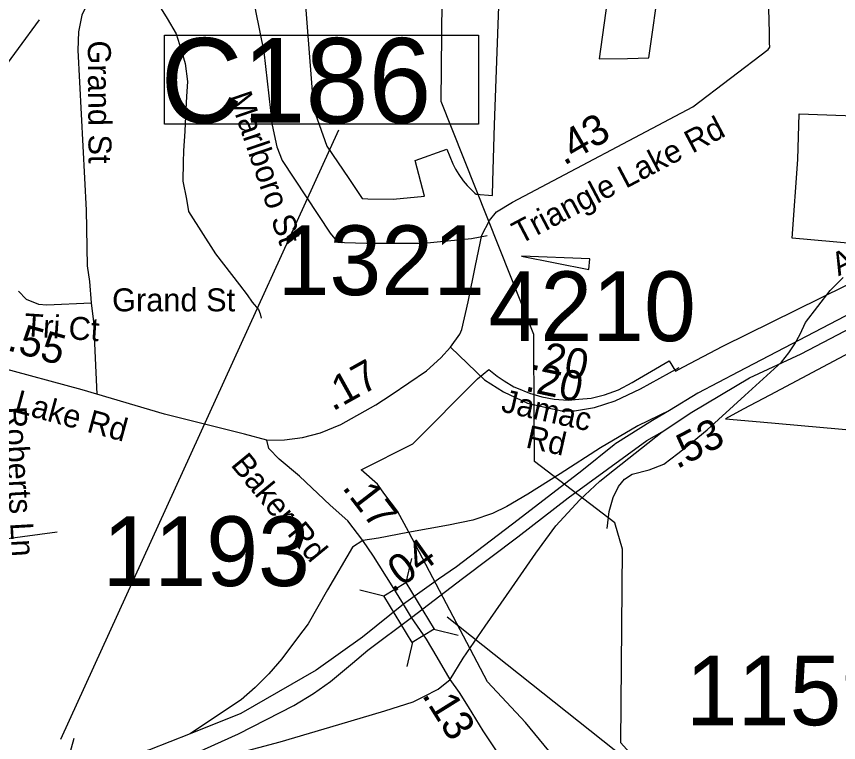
# Model space of a CAD drawing. Extents: x 1662474 to 1856135, y 779280 to 917889.
# Drawn here: x 1715769 to 1719166, y 802097 to 805097 of the extents above; entities that cross this region are included whole.
import ezdxf

# ---------------------------------------------------------------- set-up
doc = ezdxf.new("R2010")
doc.units = 0
for name, color, linetype in [('Cogo Default Point CELL', 7, 'Continuous'), ('Exist Boundary Political City Limit New', 7, 'Continuous'), ('Exist Boundary Political City Limit New Hole', 7, 'Continuous'), ('Exist Hydrographic Misc Water Feature', 7, 'Continuous'), ('Exist Road Non-System Type 51', 7, 'Continuous'), ('Exist Road Non-System Type 51 Label', 7, 'Continuous'), ('Exist Road Primary Interstate Divided Center Attributed', 7, 'Continuous'), ('Exist Road Primary Interstate Mileage Hundredths English Label', 7, 'Continuous'), ('Exist Road Primary Interstate Ramp 1 Lane Attributed', 7, 'Continuous'), ('Exist Road Primary Interstate Structure Culvert CELL', 7, 'Continuous'), ('Exist Road Primary Interstate Structure Culvert Number Label', 7, 'Continuous'), ('Exist Road Secondary Mileage Tenths English Label', 7, 'Continuous'), ('Exist Road Secondary Type 51 Attributed', 7, 'Continuous'), ('Exist Road Secondary Type 51 Label', 7, 'Continuous'), ('Map Preparation Boundary City Limit Buffer Line', 7, 'Continuous'), ('Prop DGN Element Guardrail', 7, 'Continuous'), ('Prop EOT', 7, 'Continuous'), ('Prop Paved Shoulder', 7, 'Continuous'), ('Scratch_Level_2', 7, 'Continuous')]:
    doc.layers.add(name, color=color, linetype=linetype)

msp = doc.modelspace()

# ---------------------------------------------------------------- linework, layer by layer
at = {"layer": 'Exist Boundary Political City Limit New'}
for points in [[(1718045.6, 801969.6), (1717872.2, 802180.1), (1717716, 802347.3), (1717390.9, 802966.5), (1717344.1, 803053.2), (1717291.8, 803121.3), (1717260.8, 803164.7), (1717194.2, 803223.5), (1717407.5, 803330.7), (1717674.1, 803600.1), (1717721.2, 803638.4), (1717755.2, 803610.8), (1717784, 803590.9), (1717824.9, 803567.4), (1717834.9, 803562.7), (1717889.4, 803540.2), (1717939.6, 803525.2), (1717991.4, 803515.6), (1718049.2, 803512), (1718093.5, 803515.5), (1718143.9, 803520.2), (1718199, 803533.1), (1718256.9, 803554.3), (1718314, 803584.3), (1718327.5, 803592.3), (1718393, 803631.1), (1718466.8, 803674.4), (1718492.2, 803631.3), (1718524.8, 803648.7), (1718688.2, 803734.9), (1719498.1, 804134.4), (1718974.8, 804180.6), (1718997.4, 804506.2), (1719004, 804695.2), (1719269.6, 804685.4)], [(1719211.6, 803706.6), (1718882.8, 803532.8), (1718772.1, 803474.3), (1718699.4, 803434.6), (1718842, 803421.9), (1719412.5, 803371.4)]]:
    msp.add_lwpolyline(points, dxfattribs=at)
at = {"layer": 'Exist Boundary Political City Limit New Hole'}
for points in [[(1719109, 805586.9), (1719113.6, 805638.6), (1719049.2, 805565), (1719039.1, 805520.2), (1718907.5, 805583.1), (1718876.2, 805596.9), (1718498.1, 805764.1), (1718365.5, 805315.4), (1718364.5, 805311.9), (1718232, 805319.8), (1718224.5, 805261), (1718176.9, 804921.7), (1718293.4, 804923.7), (1718382.1, 804925.4), (1718427.8, 805247.4), (1718973.4, 805214.1), (1718971.6, 805161.3), (1719090.1, 805208.9), (1719021.1, 805259.2), (1719094, 805494), (1719109, 805586.9)], [(1716961, 805178.2), (1716997, 804716.4), (1717052.1, 804561.5), (1717142.6, 804427.5), (1717198.1, 804344.3), (1717220.6, 804343.2), (1717326.4, 804341.8), (1717455, 804355.2), (1717416.5, 804501.8), (1717547.2, 804548.6), (1717572.8, 804487.9), (1717584.1, 804465.4), (1717597.1, 804443.6), (1717615.4, 804417.8), (1717631.6, 804398.4), (1717649.1, 804380.2), (1717663, 804367.2), (1717668.4, 804362.2), (1717736, 804356.7), (1717737.9, 804416.8), (1717745, 804648.8), (1717768, 805291.6)], [(1717855.9, 804106.9), (1718134.5, 804051.8), (1718138.6, 804095.8), (1717855.9, 804106.9)]]:
    msp.add_lwpolyline(points, dxfattribs=at)
at = {"layer": 'Exist Hydrographic Misc Water Feature'}
for points in [[(1717907.8, 803443.9), (1717907.3, 803783), (1717524.2, 804746), (1717528.2, 805162.8), (1717640.3, 805593.8), (1717937.3, 806093.3), (1717963.3, 806184.6), (1717955.3, 806309.5), (1717907.3, 806418.8), (1717717.3, 806629.5)], [(1716360.8, 805138.9), (1716391.7, 805088.3), (1716428.7, 805025.5), (1716449.4, 804959), (1716466.3, 804902.7), (1716476.8, 804828.4), (1716471.7, 804766.5), (1716468.2, 804684.5), (1716465.2, 804622.5), (1716459.6, 804542.5), (1716458.6, 804494.5), (1716457.3, 804416.4), (1716471.9, 804342), (1716480.8, 804291.8), (1716591.5, 804115.6), (1716691.1, 803987.6), (1716722.4, 803947), (1716743.7, 803916.6), (1716769.2, 803886.1), (1716776.8, 803867.9), (1716780.5, 803849.8)], [(1718209.4, 802981.4), (1718218, 803051.4), (1718234.6, 803109.2), (1718257, 803155), (1718281.4, 803184.8), (1718313.5, 803206.5), (1718383.8, 803223.9), (1718444, 803247.3), (1718502.4, 803290.8), (1718560.9, 803338.2), (1718623.4, 803389.6), (1718778.8, 803530.3), (1718930.2, 803668.9), (1718960.5, 803706.6), (1718984.8, 803744.3), (1719007.2, 803784.1), (1719029.6, 803832), (1719131, 803965), (1719185.6, 804018.5)], [(1718868.3, 801465.9), (1718812.3, 801673.8), (1718696.3, 801768.1), (1718472.3, 801867.8), (1718266.2, 802095.2), (1718273.3, 802895.9), (1718241.3, 803004.9), (1717910.3, 803257.8), (1717907.8, 803443.9)]]:
    msp.add_lwpolyline(points, dxfattribs=at)
at = {"layer": 'Exist Road Non-System Type 51'}
msp.add_line((1715723, 802939.2), (1715937.8, 802967.9), dxfattribs=at)
for points in [[(1716237.8, 805419), (1716224.1, 805389.9), (1716186.2, 805324.5), (1716105.1, 805219.5), (1716068.9, 805162.6), (1716039.9, 805102.2), (1716025.9, 805033.2), (1716023.6, 804958.4), (1716057.4, 804296.2), (1716061.1, 804066.5), (1716070.8, 804002), (1716078.6, 803913.8)], [(1716734, 805376.8), (1716732.1, 805321.4), (1716744.8, 805211.7), (1716757.4, 805120.1), (1716791.5, 804951.4), (1716825.9, 804648.2), (1716845.9, 804558.7), (1716867.6, 804502), (1717065.2, 804202), (1717085.5, 804178.9), (1717107, 804166.5), (1717124.6, 804162.4), (1717216.1, 804160.2), (1717450.9, 804161), (1717649.5, 804179.2), (1717713.9, 804191.5)], [(1715777.6, 803962.1), (1715808.9, 803929.5), (1715860.4, 803908.9), (1715895.5, 803905.4), (1716078.6, 803913.8)], [(1716078.6, 803913.8), (1716087.1, 803835.1), (1716101, 803536.1)]]:
    msp.add_lwpolyline(points, dxfattribs=at)
at = {"layer": 'Exist Road Primary Interstate Divided Center Attributed'}
for points in [[(1721159.6, 804831), (1720371, 804447.9), (1719985.3, 804257.2), (1719529, 804024.4), (1719223, 803873.5), (1718752.7, 803628.3), (1718585.1, 803541), (1718467.1, 803468.6)], [(1718437.4, 803380.4), (1718560.3, 803462.7), (1718798.4, 803604.1), (1719011.6, 803703.7), (1719282.9, 803844.8), (1719520.9, 803963.7), (1720413, 804416.2), (1720858.9, 804615.4)], [(1718467.1, 803468.6), (1718396.7, 803427), (1718241.8, 803329.6), (1718239.3, 803327.7), (1718105.2, 803219.7), (1717842.4, 803017.4), (1717587, 802823.1), (1717513.7, 802771.5), (1717368.9, 802668.4)], [(1717401.6, 802613.8), (1717611.8, 802775.5), (1717840.4, 802947), (1718049.6, 803107.7), (1718373.9, 803344.7), (1718437.4, 803380.4)], [(1717368.9, 802668.4), (1717199.3, 802532.5), (1717008.4, 802396.3), (1716696.7, 802216.9), (1716486.7, 802133.2)], [(1716114.4, 801939.5), (1716224.3, 801968.2), (1716290.5, 801986.9), (1716475.8, 802038.5), (1716687.3, 802133.7), (1716915.1, 802249.9), (1716997.3, 802299.9), (1717066.7, 802348.6), (1717157.6, 802425), (1717221.8, 802479), (1717401.6, 802613.8)], [(1716486.7, 802133.2), (1716319.2, 802067), (1716013.2, 801976.9), (1715983.2, 801968.2), (1715870.8, 801945.7), (1715679.7, 801921.7), (1715473.7, 801907.1), (1715410.4, 801907.1), (1714986.8, 801893.7), (1714650.6, 801881), (1714517.9, 801872.2), (1714393.9, 801862.8), (1714215.5, 801837.2), (1714009.7, 801788.4)]]:
    msp.add_lwpolyline(points, dxfattribs=at)
at = {"layer": 'Exist Road Primary Interstate Ramp 1 Lane Attributed'}
for points in [[(1718467.1, 803468.6), (1718336.2, 803405.2), (1718183.2, 803314.6), (1718016.3, 803207.2), (1717882.1, 803123.6), (1717795.6, 803072.9), (1717736, 803043.1), (1717655.5, 803016.2), (1717554.1, 802995.4), (1717387.1, 802965.5), (1717264.9, 802941.7), (1717200.8, 802932.2)], [(1717560.8, 802357), (1717615.3, 802446.2), (1717706.2, 802577.7), (1717816.5, 802735.8), (1717914.9, 802879), (1717998.4, 802992.4), (1718096.8, 803099.8), (1718180.2, 803177.3), (1718239.9, 803225.1), (1718437.4, 803380.4)], [(1717200.8, 802932.2), (1717157.2, 802904.4), (1717054, 802727.9), (1716974.7, 802588.1), (1716931, 802530), (1716865.4, 802443.4), (1716811.7, 802380.8), (1716755.1, 802324.1), (1716698.4, 802273.4), (1716609, 802213.7), (1716486.7, 802133.2)], [(1716114.4, 801939.5), (1716373.4, 801978.1), (1716614.9, 802034.7), (1716859.4, 802100.4), (1717100.9, 802172), (1717291.7, 802228.7), (1717408, 802265.8), (1717452.7, 802287.6), (1717512.2, 802317.3), (1717560.8, 802357)]]:
    msp.add_lwpolyline(points, dxfattribs=at)
at = {"layer": 'Exist Road Primary Interstate Structure Culvert CELL'}
msp.add_line((1716007, 802114.4), (1715983.9, 802034.4), dxfattribs=at)
at = {"layer": 'Exist Road Primary Interstate Structure Culvert Number Label'}
msp.add_line((1715953, 802111.5), (1717101.4, 804628.3), dxfattribs=at)
msp.add_lwpolyline([(1716381.3, 805020.4), (1717679.1, 805020.4), (1717679.1, 804651.7), (1716381.3, 804651.7)], close=True, dxfattribs=at)
at = {"layer": 'Exist Road Secondary Type 51 Attributed'}
for points in [[(1717563.2, 803730.7), (1717601.8, 803783.7), (1717610.1, 803803.6), (1717635.7, 803917.3), (1717665.7, 804068.6), (1717692.1, 804193.5), (1717724.3, 804253.9), (1717752.6, 804289.4), (1717819.4, 804330.4), (1718564.2, 804723.6), (1718875.4, 804960.9), (1718882, 804970.2), (1718880.7, 804988.7), (1718880.7, 805037.6), (1718879.4, 805072), (1718875.8, 805265.4)], [(1716803.4, 803346.2), (1716711.2, 803370.6), (1716381.1, 803454.1), (1716040.6, 803554), (1715693.9, 803647.7), (1715300.5, 803761), (1715208.4, 803781.4), (1714816.2, 803832.5), (1714417.1, 803863.7), (1714009.1, 803893.1), (1713810.8, 803901.7)], [(1716803.4, 803346.2), (1716876.8, 803348.1), (1716950.6, 803357.1), (1717026.3, 803376.9), (1717109.6, 803411.1), (1717254.6, 803491.9), (1717317.8, 803533.5), (1717463.3, 803633.2), (1717523.3, 803686.8), (1717563.2, 803730.7)], [(1717563.2, 803730.7), (1717703.9, 803595.5), (1717782.2, 803546.2), (1717880.8, 803499.8), (1717965, 803479.5), (1718023.3, 803467.1), (1718075.2, 803467.9), (1718158.1, 803481.6), (1718243.1, 803508.6), (1718347.9, 803557.8), (1718508.2, 803646.2)], [(1717200.8, 802932.2), (1717138.3, 803013.5), (1717065.8, 803078.1), (1716938.7, 803197.9), (1716855, 803268.3), (1716812.8, 803312.4), (1716803.4, 803346.2)], [(1717368.9, 802668.4), (1717322.3, 802744.7), (1717244.4, 802866.7), (1717200.8, 802932.2)], [(1717401.6, 802613.8), (1717368.9, 802668.4)], [(1717560.8, 802357), (1717507.7, 802450.2), (1717464.1, 802523.6), (1717401.6, 802613.8)], [(1717772, 802033.7), (1717698.1, 802144.8), (1717637.1, 802244), (1717599.4, 802304.4), (1717560.8, 802357)]]:
    msp.add_lwpolyline(points, dxfattribs=at)
at = {"layer": 'Map Preparation Boundary City Limit Buffer Line'}
for points in [[(1719109, 805586.9), (1719113.6, 805638.6), (1719049.2, 805565), (1719039.1, 805520.2), (1718907.5, 805583.1), (1718876.2, 805596.9), (1718498.1, 805764.1), (1718365.5, 805315.4), (1718364.5, 805311.9), (1718232, 805319.8), (1718224.5, 805261), (1718176.9, 804921.7), (1718293.4, 804923.7), (1718382.1, 804925.4), (1718427.8, 805247.4), (1718973.4, 805214.1), (1718971.6, 805161.3), (1719090.1, 805208.9), (1719021.1, 805259.2), (1719094, 805494), (1719109, 805586.9)], [(1716961, 805178.2), (1716997, 804716.4), (1717052.1, 804561.5), (1717142.6, 804427.5), (1717198.1, 804344.3), (1717220.6, 804343.2), (1717326.4, 804341.8), (1717455, 804355.2), (1717416.5, 804501.8), (1717547.2, 804548.6), (1717572.8, 804487.9), (1717584.1, 804465.4), (1717597.1, 804443.6), (1717615.4, 804417.8), (1717631.6, 804398.4), (1717649.1, 804380.2), (1717663, 804367.2), (1717668.4, 804362.2), (1717736, 804356.7), (1717737.9, 804416.8), (1717745, 804648.8), (1717768, 805291.6)], [(1718045.6, 801969.6), (1717872.2, 802180.1), (1717716, 802347.3), (1717390.9, 802966.5), (1717344.1, 803053.2), (1717291.8, 803121.3), (1717260.8, 803164.7), (1717194.2, 803223.5), (1717407.5, 803330.7), (1717674.1, 803600.1), (1717721.2, 803638.4), (1717755.2, 803610.8), (1717784, 803590.9), (1717824.9, 803567.4), (1717834.9, 803562.7), (1717889.4, 803540.2), (1717939.6, 803525.2), (1717991.4, 803515.6), (1718049.2, 803512), (1718093.5, 803515.5), (1718143.9, 803520.2), (1718199, 803533.1), (1718256.9, 803554.3), (1718314, 803584.3), (1718327.5, 803592.3), (1718393, 803631.1), (1718466.8, 803674.4), (1718492.2, 803631.3), (1718524.8, 803648.7), (1718688.2, 803734.9), (1719498.1, 804134.4), (1718974.8, 804180.6), (1718997.4, 804506.2), (1719004, 804695.2), (1719269.6, 804685.4)], [(1717855.9, 804106.9), (1718134.5, 804051.8), (1718138.6, 804095.8), (1717855.9, 804106.9)], [(1719211.6, 803706.6), (1718882.8, 803532.8), (1718772.1, 803474.3), (1718699.4, 803434.6), (1718842, 803421.9), (1719412.5, 803371.4)]]:
    msp.add_lwpolyline(points, dxfattribs=at)
at = {"layer": 'Prop EOT'}
for p, q in [((1717402.1, 802857.7), (1717377.6, 802757.8)), ((1717187.7, 802727.6), (1717287.7, 802703.1)), ((1717494.2, 802564.9), (1717594.1, 802540.5)), ((1717406.2, 802511.5), (1717381.8, 802411.6))]:
    msp.add_line(p, q, dxfattribs=at)
msp.add_lwpolyline([(1717377.6, 802757.8), (1717494.6, 802565.2), (1717404.6, 802510.5), (1717287.7, 802703.1)], close=True, dxfattribs=at)
at = {"layer": 'Prop Paved Shoulder'}
msp.add_lwpolyline([(1717548.8, 802616.6), (1718781.5, 801637.7), (1719796.7, 801528.9)], dxfattribs=at)
at = {"layer": 'Scratch_Level_2'}
msp.add_line((1712420.6, 800394.1), (1715864.4, 805083.3), dxfattribs=at)

# ---------------------------------------------------------------- texts
at = {"layer": 'Cogo Default Point CELL'}
for s, p in [('1321', (1716848.2, 803945.7)), ('4210', (1717719.9, 803755.6)), ('1193', (1716125.1, 802743.7)), ('1159', (1718535.2, 802168.6))]:
    msp.add_text(s, height=288, dxfattribs=at).set_placement(p)
at = {"layer": 'Exist Road Non-System Type 51 Label'}
for s, rotation, p in [('Grand St', 270.3525, (1716064.3, 804997.5)), ('Marlboro St', 288.863, (1716646.4, 804768.1)), ('Armory Dr', 26.3731, (1719166, 804023.1)), ('Tri Ct', 356.148, (1715799.1, 803776.1)), ('Roberts Ln', 273.2819, (1715716.1, 803483.7))]:
    msp.add_text(s, height=95, rotation=rotation, dxfattribs=at).set_placement(p)
msp.add_text('Grand St', height=95, dxfattribs=at).set_placement((1716164.6, 803878.6))
at = {"layer": 'Exist Road Primary Interstate Mileage Hundredths English Label'}
for s, rotation, p in [('.53', 27.5064, (1718498.4, 803225.7)), ('.04', 35.4634, (1717322.6, 802712.2))]:
    msp.add_text(s, height=125, rotation=rotation, dxfattribs=at).set_placement(p)
at = {"layer": 'Exist Road Primary Interstate Structure Culvert Number Label'}
msp.add_text('C186', height=350, dxfattribs=at).set_placement((1716365.2, 804657.8))
at = {"layer": 'Exist Road Secondary Mileage Tenths English Label'}
for s, rotation, p in [('.43', 30.2506, (1718031.9, 804479.1)), ('.55', 343.9372, (1715726.6, 803719.3)), ('.20', 348.0435, (1717889.5, 803641.2)), ('.20', 348.0435, (1717866.8, 803550.6))]:
    msp.add_text(s, height=125, rotation=rotation, dxfattribs=at).set_placement(p)
at = {"layer": 'Exist Road Secondary Type 51 Label'}
for s, rotation, p in [('Triangle Lake Rd', 27.826, (1717849.7, 804153.7)), ('Triangle Lake Rd', 344.763, (1715279.2, 803593.7)), ('Jamac', 347.314, (1717767.8, 803465.1)), (' Rd', 347.314, (1717835.3, 803324.8)), ('Baker Rd', 309.4278, (1716651.5, 803243.5))]:
    msp.add_text(s, height=95, rotation=rotation, dxfattribs=at).set_placement(p)
at = {"layer": 'Prop DGN Element Guardrail'}
for s, rotation, p in [('.17', 29.1294, (1717076, 803464)), ('.17', 307.5348, (1717112.2, 803150.1)), ('.13', 301.9209, (1717442.7, 802293.3))]:
    msp.add_text(s, height=125, rotation=rotation, dxfattribs=at).set_placement(p)

doc.saveas('drawing.dxf')
